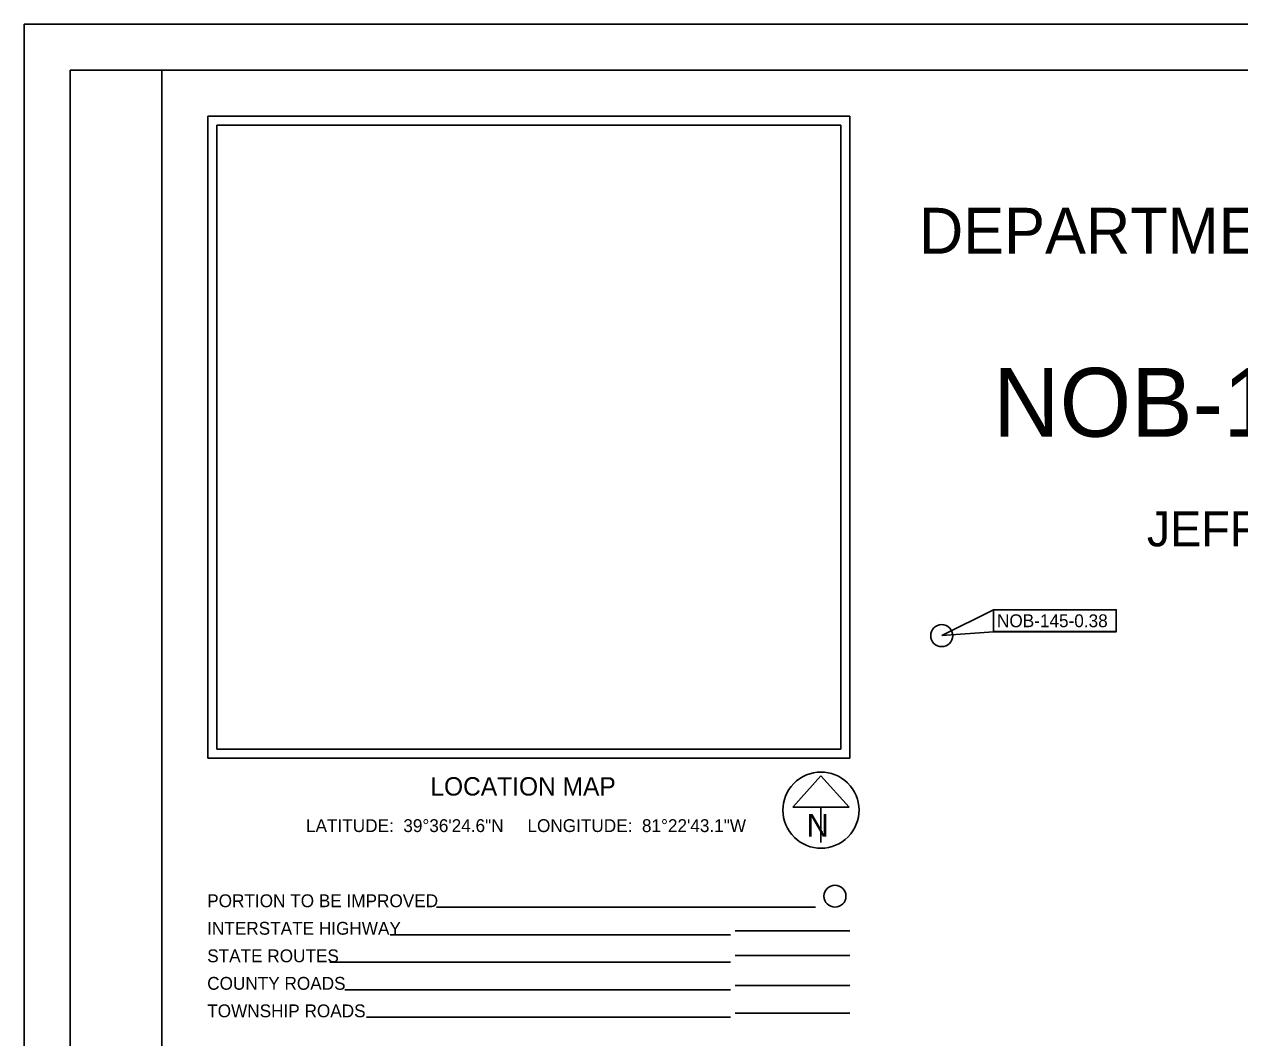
# Model space of a CAD drawing. Extents: x -10.5 to 40.6, y -3.2 to 22.
# Drawn here: x 0 to 13.25, y 10.95 to 22 of the extents above; entities that cross this region are included whole.
import ezdxf

# ---------------------------------------------------------------- set-up
doc = ezdxf.new("R2010")
doc.units = 0
for name, color, linetype in [('SH_Border', 7, 'Continuous'), ('SH_Cut_Line', 7, 'Continuous'), ('SH_Data', 7, 'Continuous'), ('SH_Text', 7, 'Continuous')]:
    doc.layers.add(name, color=color, linetype=linetype)

msp = doc.modelspace()

# ---------------------------------------------------------------- linework, layer by layer
at = {"layer": 'SH_Border'}
for points in [[(0.5, 21.5), (1.5, 21.5), (1.5, 0.5), (0.5, 0.5)], [(1.5, 21.5), (33.5, 21.5), (33.5, 0.5), (1.5, 0.5)]]:
    msp.add_lwpolyline(points, close=True, dxfattribs=at)
at = {"layer": 'SH_Cut_Line'}
msp.add_lwpolyline([(0, 0), (34, 0), (34, 22), (0, 22)], close=True, dxfattribs=at)
at = {"layer": 'SH_Data'}
for p, q in [((2, 21), (9, 21)), ((2, 21), (2, 14)), ((9, 21), (9, 14)), ((2.1, 20.9), (2.1, 14.1)), ((2.1, 20.9), (8.9, 20.9)), ((8.9, 20.9), (8.9, 14.1)), ((2.1, 14.1), (8.9, 14.1)), ((2.1, 14.1), (2.1, 14.1)), ((2, 14), (9, 14)), ((8.685, 13.809), (8.377, 13.468)), ((8.992, 13.468), (8.685, 13.809)), ((8.377, 13.468), (8.992, 13.468)), ((8.685, 13.468), (8.685, 13.081)), ((8.685, 13.435), (8.685, 13.435)), ((8.685, 13.435), (8.685, 13.435)), ((8.626, 12.377), (4.494, 12.377)), ((7.7, 12.077), (3.99, 12.077)), ((9, 12.121), (7.75, 12.121)), ((9, 11.849), (7.75, 11.849)), ((7.7, 11.777), (3.329, 11.777)), ((7.7, 11.477), (3.496, 11.477)), ((9, 11.522), (7.75, 11.522)), ((7.7, 11.177), (3.731, 11.177)), ((9, 11.222), (7.75, 11.222))]:
    msp.add_line(p, q, dxfattribs=at)
msp.add_arc((8.685, 13.435), 0.415, 129.7798, 129.7633, dxfattribs=at)
at = {"layer": 'SH_Text'}
for points in [[(10.002, 15.337), (10.567, 15.619), (10.567, 15.379)], [(11.905, 15.619), (10.567, 15.619), (10.567, 15.379), (11.905, 15.379)], [(10.567, 15.619), (11.905, 15.619), (11.905, 15.381), (10.567, 15.381)]]:
    msp.add_lwpolyline(points, close=True, dxfattribs=at)
for centre in [(10.002, 15.337), (8.838, 12.497)]:
    msp.add_circle(centre, 0.12, dxfattribs=at)

# ---------------------------------------------------------------- texts
at = {"layer": 'SH_Data'}
msp.add_text('N', height=0.25, dxfattribs=at).set_placement((8.529, 13.144))
at = {"layer": 'SH_Text'}
for s, height, p in [('DEPARTMENT OF TRANSPORTATION', 0.5, (9.753, 19.5)), ('NOB-145/147-0.38/18.42', 0.75, (10.563, 17.505)), ('JEFFERSON AND BEAVER TOWNSHIPS', 0.38, (12.238, 16.31)), ('NOB-145-0.38', 0.14, (10.604, 15.429)), ('LOCATION MAP', 0.2, (4.427, 13.594)), ('LATITUDE:  39°36\'24.6"N     LONGITUDE:  81°22\'43.1"W', 0.14, (3.071, 13.196)), ('PORTION TO BE IMPROVED', 0.14, (1.994, 12.377)), ('INTERSTATE HIGHWAY', 0.14, (1.994, 12.077)), ('STATE ROUTES', 0.14, (1.994, 11.777)), ('COUNTY ROADS', 0.14, (1.994, 11.477)), ('TOWNSHIP ROADS', 0.14, (1.994, 11.177))]:
    msp.add_text(s, height=height, dxfattribs=at).set_placement(p)

doc.saveas('drawing.dxf')
